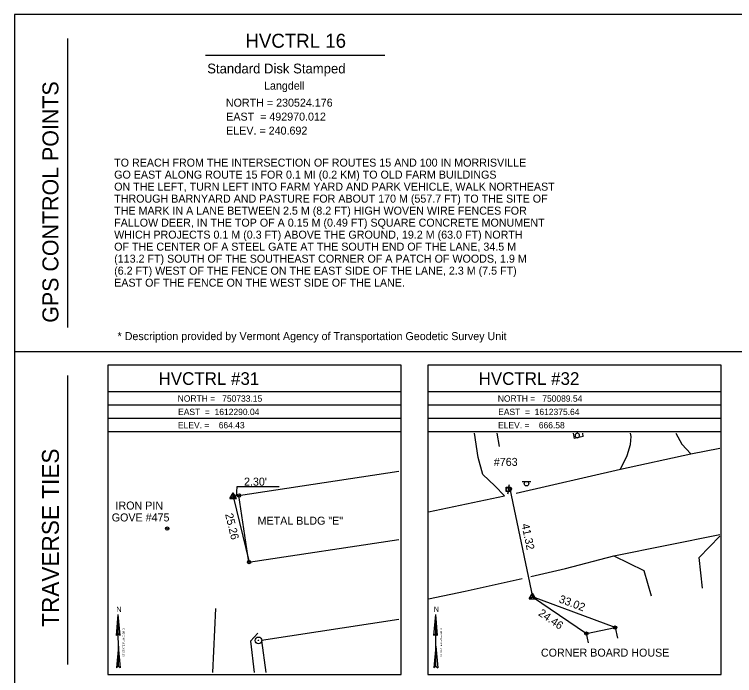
# Model space of a CAD drawing. Extents: x 1612431 to 1613071, y 750572 to 750992.
# Drawn here: x 1612431.1 to 1612701.1, y 750744.3 to 750992.1 of the extents above; entities that cross this region are included whole.
import ezdxf

# ---------------------------------------------------------------- set-up
doc = ezdxf.new("R2010")
doc.units = 0
for name, color, linetype in [('C_C', 7, 'Continuous'), ('CBP', 7, 'Continuous'), ('CPSM', 7, 'Continuous'), ('Default', 7, 'Continuous'), ('LAHR', 7, 'Continuous'), ('LBC', 7, 'Continuous'), ('Level 1', 7, 'Continuous'), ('Level 2', 7, 'Continuous'), ('Level 63', 7, 'Continuous'), ('LW', 7, 'Continuous'), ('M_C', 7, 'Continuous'), ('MPIR', 7, 'Continuous'), ('NBL2', 7, 'Continuous'), ('NNA_P', 7, 'Continuous'), ('PET', 7, 'Continuous'), ('RDG', 7, 'Continuous'), ('RDP', 7, 'Continuous'), ('RGP', 7, 'Continuous'), ('SSGN', 7, 'Continuous'), ('U_C', 7, 'Continuous'), ('UP', 7, 'Continuous')]:
    doc.layers.add(name, color=color, linetype=linetype)

msp = doc.modelspace()

# ---------------------------------------------------------------- linework, layer by layer
at = {"layer": 'CBP'}
for centre, radius in [((1612515.38, 750811.78), 0.625), ((1612616.87, 750814.22), 0.625), ((1612616.87, 750814.22), 0.0833), ((1612515.38, 750811.78), 0.0833), ((1612519.08, 750786.85), 0.625), ((1612519.08, 750786.85), 0.0833), ((1612656.34, 750762.28), 0.625), ((1612656.34, 750762.28), 0.0833), ((1612645.6, 750759.99), 0.625), ((1612645.6, 750759.99), 0.0833)]:
    msp.add_circle(centre, radius, dxfattribs=at)
at = {"layer": 'CPSM'}
for p, q in [((1612511.86, 750810.67), (1612513.11, 750812.84)), ((1612514.36, 750810.67), (1612513.11, 750812.84)), ((1612513.11, 750811.39), (1612513.11, 750812.84)), ((1612511.86, 750810.67), (1612513.11, 750811.39)), ((1612511.86, 750810.67), (1612514.36, 750810.67)), ((1612513.11, 750811.39), (1612513.11, 750811.39)), ((1612513.11, 750811.39), (1612514.36, 750810.67)), ((1612624.14, 750773.06), (1612625.39, 750775.23)), ((1612626.64, 750773.06), (1612625.39, 750775.23)), ((1612625.39, 750773.78), (1612625.39, 750775.23)), ((1612624.14, 750773.06), (1612625.39, 750773.78)), ((1612624.14, 750773.06), (1612626.64, 750773.06)), ((1612625.39, 750773.78), (1612625.39, 750773.78)), ((1612625.39, 750773.78), (1612626.64, 750773.06))]:
    msp.add_line(p, q, dxfattribs=at)
at = {"layer": 'Default'}
for p, q in [((1612514.57, 750815.06), (1612514.24, 750811.59)), ((1612530.37, 750815.06), (1612514.57, 750815.06)), ((1612616.87, 750814.22), (1612625.39, 750773.78)), ((1612515.38, 750811.78), (1612513.11, 750811.39)), ((1612513.11, 750811.39), (1612519.08, 750786.85)), ((1612625.39, 750773.78), (1612645.6, 750759.99)), ((1612656.34, 750762.28), (1612625.39, 750773.78))]:
    msp.add_line(p, q, dxfattribs=at)
at = {"layer": 'LAHR'}
msp.add_lwpolyline([(1612612.04, 750835.09), (1612612.89, 750830.16)], dxfattribs=at)
at = {"layer": 'LBC'}
for p, q in [((1612656.34, 750762.28), (1612657.19, 750758.3)), ((1612646.32, 750756.58), (1612645.6, 750759.99))]:
    msp.add_line(p, q, dxfattribs=at)
for points in [[(1612515.14, 750811.83), (1612575.19, 750820.89)], [(1612515.14, 750811.83), (1612518.92, 750786.85), (1612575.19, 750795.31)], [(1612575.19, 750765.24), (1612523.75, 750757.46), (1612525.36, 750745.41)], [(1612645.6, 750759.99), (1612656.34, 750762.28)]]:
    msp.add_lwpolyline(points, dxfattribs=at)
at = {"layer": 'Level 1'}
msp.add_line((1612502.75, 750976.88), (1612570.03, 750976.88), dxfattribs=at)
at = {"layer": 'LW'}
for points in [[(1612640.63, 750835.09), (1612640.93, 750833.21)], [(1612644.38, 750833.94), (1612640.93, 750833.21)], [(1612644.38, 750833.94), (1612644.18, 750835.09)]]:
    msp.add_lwpolyline(points, dxfattribs=at)
at = {"layer": 'MPIR'}
for radius in [0.625, 0.0833]:
    msp.add_circle((1612488.44, 750799.39), radius, dxfattribs=at)
at = {"layer": 'NBL2'}
for p, q in [((1612451.13, 750874.8), (1612451.13, 750983.13)), ((1612431.13, 750865.8), (1613071.13, 750865.8)), ((1612451.13, 750748.46), (1612451.13, 750856.8)), ((1612576.13, 750850.63), (1612466.13, 750850.63)), ((1612696.13, 750850.63), (1612586.13, 750850.63)), ((1612576.13, 750845.63), (1612466.13, 750845.63)), ((1612696.13, 750845.63), (1612586.13, 750845.63)), ((1612576.13, 750840.63), (1612466.13, 750840.63)), ((1612696.13, 750840.63), (1612586.13, 750840.63)), ((1612576.13, 750835.63), (1612466.13, 750835.63)), ((1612696.13, 750835.63), (1612586.13, 750835.63))]:
    msp.add_line(p, q, dxfattribs=at)
for points in [[(1612431.13, 750572.13), (1613071.13, 750572.13), (1613071.13, 750992.13), (1612431.13, 750992.13)], [(1612466.13, 750744.63), (1612576.13, 750744.63), (1612576.13, 750860.63), (1612466.13, 750860.63)], [(1612586.13, 750744.63), (1612696.13, 750744.63), (1612696.13, 750860.63), (1612586.13, 750860.63)]]:
    msp.add_lwpolyline(points, close=True, dxfattribs=at)
at = {"layer": 'NNA_P'}
for p, q in [((1612469.4, 750759.34), (1612470.09, 750767.13)), ((1612470.1, 750747.75), (1612470.09, 750767.13)), ((1612470.79, 750759.34), (1612470.09, 750767.13)), ((1612588.41, 750759.34), (1612589.1, 750767.13)), ((1612589.1, 750747.75), (1612589.1, 750767.13)), ((1612589.79, 750759.34), (1612589.1, 750767.13)), ((1612469.4, 750759.34), (1612470.09, 750760.1)), ((1612470.79, 750759.34), (1612470.09, 750760.1)), ((1612588.41, 750759.34), (1612589.1, 750760.1)), ((1612589.8, 750759.34), (1612589.1, 750760.1)), ((1612470.1, 750755.28), (1612469.37, 750747.12)), ((1612470.09, 750755.28), (1612470.82, 750747.12)), ((1612589.1, 750755.28), (1612588.38, 750747.12)), ((1612589.1, 750755.28), (1612589.82, 750747.12)), ((1612470.1, 750747.75), (1612469.37, 750747.12)), ((1612470.1, 750747.75), (1612470.82, 750747.12)), ((1612589.1, 750747.75), (1612588.38, 750747.12)), ((1612589.1, 750747.75), (1612589.82, 750747.12))]:
    msp.add_line(p, q, dxfattribs=at)
at = {"layer": 'PET'}
for points in [[(1612619.27, 750812.68), (1612658.34, 750821.71), (1612684.75, 750827.37), (1612695.62, 750829.5)], [(1612586.32, 750805.69), (1612614.83, 750811.65)], [(1612624.69, 750781.44), (1612637.75, 750784.36), (1612655.8, 750789.12), (1612695.62, 750797.16)], [(1612586.32, 750773.01), (1612600.17, 750775.97), (1612621.48, 750780.73)]]:
    msp.add_lwpolyline(points, dxfattribs=at)
at = {"layer": 'RDG'}
for points in [[(1612505.47, 750745.41), (1612506.64, 750769.45)], [(1612522.44, 750760.15), (1612519.66, 750757.19), (1612521, 750745.41)]]:
    msp.add_lwpolyline(points, dxfattribs=at)
at = {"layer": 'RDP'}
for points in [[(1612614.83, 750811.65), (1612611.2, 750815.4), (1612606.78, 750819.64), (1612604.94, 750826), (1612603.58, 750835.09)], [(1612658.34, 750821.71), (1612660.84, 750826.78), (1612662.07, 750830.94), (1612662.33, 750833.91), (1612662.06, 750835.09)], [(1612679.1, 750835.09), (1612681.39, 750831), (1612684.75, 750827.37)], [(1612689.07, 750777.02), (1612687.86, 750788.5), (1612695.62, 750796.52)], [(1612655.8, 750789.12), (1612667.16, 750783.63), (1612669.79, 750774.14)]]:
    msp.add_lwpolyline(points, dxfattribs=at)
at = {"layer": 'RGP'}
msp.add_line((1612522.63, 750757.47), (1612522.63, 750757.47), dxfattribs=at)
for radius in [1.25, 0.0833]:
    msp.add_circle((1612522.63, 750757.47), radius, dxfattribs=at)
at = {"layer": 'SSGN'}
for p, q in [((1612642.35, 750835.09), (1612641.94, 750835.09)), ((1612642.15, 750834.28), (1612642.15, 750834.28)), ((1612621.46, 750817.06), (1612624.79, 750817.06)), ((1612623.11, 750816.23), (1612623.11, 750816.23))]:
    msp.add_line(p, q, dxfattribs=at)
msp.add_circle((1612623.11, 750816.23), 0.833, dxfattribs=at)
msp.add_arc((1612642.15, 750834.28), 0.833, 103.9855, 76.0145, dxfattribs=at)
at = {"layer": 'UP'}
for p, q in [((1612615.5, 750813.3), (1612615.5, 750814.96)), ((1612615.5, 750814.96), (1612617.16, 750814.96)), ((1612616.58, 750815.8), (1612616.33, 750814.96)), ((1612617.16, 750814.96), (1612617.16, 750813.3)), ((1612617.16, 750813.3), (1612615.5, 750813.3)), ((1612616.08, 750812.46), (1612616.33, 750813.3)), ((1612616.33, 750814.13), (1612616.33, 750814.13))]:
    msp.add_line(p, q, dxfattribs=at)
msp.add_circle((1612616.33, 750814.13), 0.833, dxfattribs=at)

# ---------------------------------------------------------------- texts
at = {"layer": 'C_C'}
for s, p in [("2.30'", (1612517.21, 750815.47)), ('METAL BLDG "E"', (1612522.3, 750800.84)), ('CORNER BOARD HOUSE', (1612628.52, 750751.38))]:
    msp.add_text(s, height=3, dxfattribs=at).set_placement(p)
at = {"layer": 'Default'}
for s, rotation, p in [('25.26', 283.6801, (1612510.1, 750804.74)), ('41.32', 281.904, (1612621.2, 750800.96)), ('33.02', 339.6024, (1612635.02, 750771.8)), ('24.46', 325.6746, (1612627.28, 750767.05))]:
    msp.add_text(s, height=3, rotation=rotation, dxfattribs=at).set_placement(p)
at = {"layer": 'Level 1'}
for s, height, p in [('Standard Disk Stamped', 3.6714, (1612503.42, 750970.01)), ('* Description provided by Vermont Agency of Transportation Geodetic Survey Unit', 3, (1612469.81, 750870.03))]:
    msp.add_text(s, height=height, dxfattribs=at).set_placement(p)
at = {"layer": 'Level 2'}
for s, p in [('TO REACH FROM THE INTERSECTION OF ROUTES 15 AND 100 IN MORRISVILLE ', (1612468.53, 750935.07)), ('GO EAST ALONG ROUTE 15 FOR 0.1 MI (0.2 KM) TO OLD FARM BUILDINGS ', (1612468.53, 750930.57)), ('ON THE LEFT, TURN LEFT INTO FARM YARD AND PARK VEHICLE, WALK NORTHEAST ', (1612468.53, 750926.07)), ('THROUGH BARNYARD AND PASTURE FOR ABOUT 170 M (557.7 FT) TO THE SITE OF', (1612468.53, 750921.57)), ('THE MARK IN A LANE BETWEEN 2.5 M (8.2 FT) HIGH WOVEN WIRE FENCES FOR', (1612468.53, 750917.07)), ('FALLOW DEER, IN THE TOP OF A 0.15 M (0.49 FT) SQUARE CONCRETE MONUMENT ', (1612468.53, 750912.57)), ('WHICH PROJECTS 0.1 M (0.3 FT) ABOVE THE GROUND, 19.2 M (63.0 FT) NORTH', (1612468.53, 750908.07)), ('OF THE CENTER OF A STEEL GATE AT THE SOUTH END OF THE LANE, 34.5 M ', (1612468.53, 750903.57)), ('(113.2 FT) SOUTH OF THE SOUTHEAST CORNER OF A PATCH OF WOODS, 1.9 M ', (1612468.53, 750899.07)), ('(6.2 FT) WEST OF THE FENCE ON THE EAST SIDE OF THE LANE, 2.3 M (7.5 FT) ', (1612468.53, 750894.57)), ('EAST OF THE FENCE ON THE WEST SIDE OF THE LANE.', (1612468.53, 750890.07))]:
    msp.add_text(s, height=3, dxfattribs=at).set_placement(p)
at = {"layer": 'Level 63'}
for s, height, p in [('HVCTRL 16     ', 5.2317, (1612517.74, 750979.63)), ('Langdell                ', 3, (1612524.71, 750963.93)), ('NORTH = 230524.176 ', 3, (1612510.41, 750957.54)), ('EAST  = 492970.012 ', 3, (1612510.54, 750952.31)), ('ELEV. = 240.692    ', 3, (1612510.51, 750947.07))]:
    msp.add_text(s, height=height, dxfattribs=at).set_placement(p)
at = {"layer": 'M_C'}
for s, p in [('IRON PIN', (1612469.03, 750806.51)), ('GOVE #475', (1612467.62, 750802.06))]:
    msp.add_text(s, height=3, dxfattribs=at).set_placement(p)
at = {"layer": 'NBL2'}
for s, height, p in [('GPS CONTROL POINTS', 6, (1612447.63, 750876.55)), ('TRAVERSE TIES', 6.3332, (1612447.8, 750762.56))]:
    msp.add_text(s, height=height, rotation=90, dxfattribs=at).set_placement(p)
for s, height, p in [('     HVCTRL #31    ', 4.75, (1612476.34, 750853.25)), ('     HVCTRL #32    ', 4.75, (1612596.34, 750853.25)), ('NORTH =   750733.15 ', 2.375, (1612492.35, 750846.94)), ('NORTH =   750089.54 ', 2.375, (1612612.35, 750846.94)), ('EAST  =  1612290.04 ', 2.375, (1612492.5, 750841.94)), ('EAST  =  1612375.64 ', 2.375, (1612612.5, 750841.94)), ('ELEV. =    664.43   ', 2.375, (1612492.46, 750836.94)), ('ELEV. =    666.58   ', 2.375, (1612612.46, 750836.94))]:
    msp.add_text(s, height=height, dxfattribs=at).set_placement(p)
at = {"layer": 'NNA_P'}
for p in [(1612469.33, 750768.14), (1612588.34, 750768.14)]:
    msp.add_text('N', height=1.97, dxfattribs=at).set_placement(p)
for p in [(1612472.45, 750751.32), (1612591.45, 750751.32)]:
    msp.add_text('VT STATE PLANE GRID', height=0.7, rotation=90.0204, dxfattribs=at).set_placement(p)
at = {"layer": 'U_C'}
msp.add_text('#763', height=3, dxfattribs=at).set_placement((1612610.86, 750822.88))

doc.saveas('drawing.dxf')
